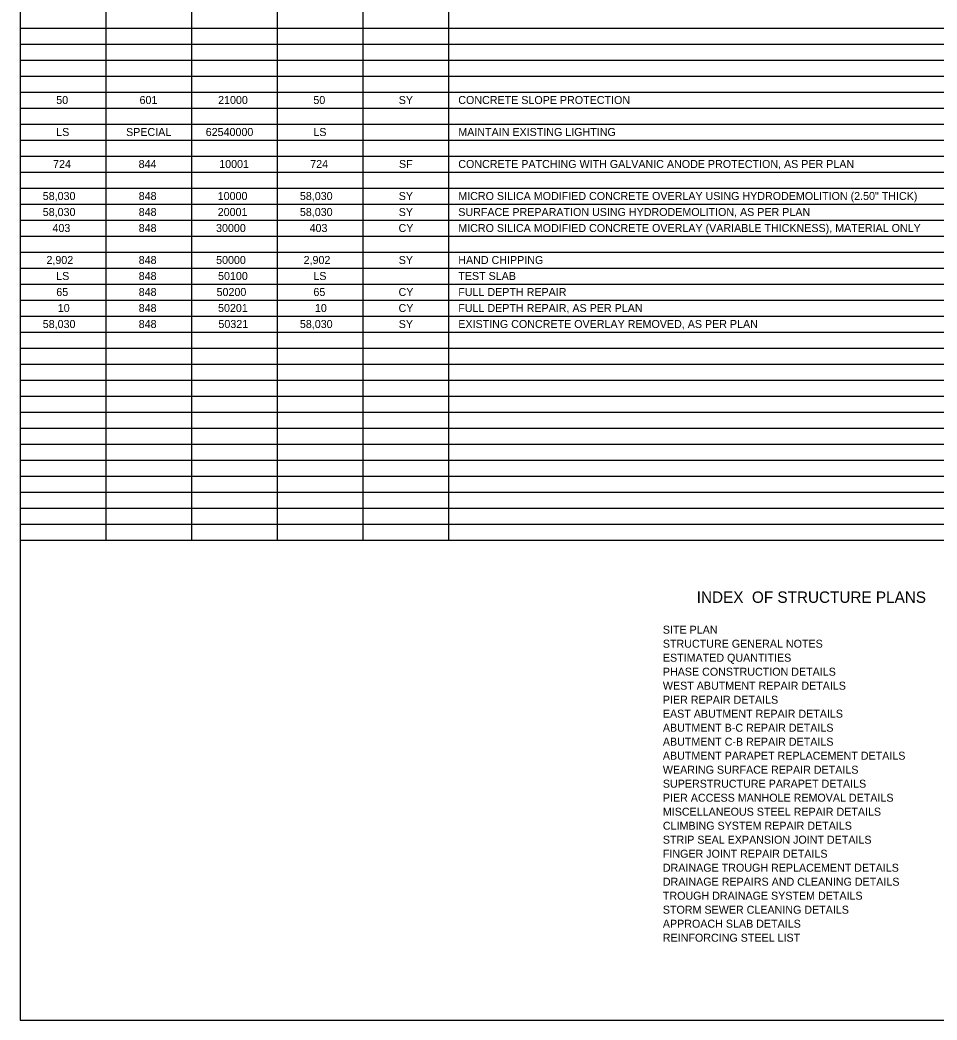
# Model space of a CAD drawing. Extents: x 100 to 128, y 64.8 to 100.
# Drawn here: x 100 to 116.05, y 64.8 to 82.3 of the extents above; entities that cross this region are included whole.
import ezdxf

# ---------------------------------------------------------------- set-up
doc = ezdxf.new("R2010")
doc.units = 0
doc.layers.add('SC_Scratch1', color=7, linetype='Continuous')
doc.layers.add('SH_Text', color=7, linetype='Continuous')

msp = doc.modelspace()

# ---------------------------------------------------------------- linework, layer by layer
at = {"layer": 'SC_Scratch1'}
for p, q in [((100, 73.2), (100, 64.8)), ((100, 64.8), (128, 64.8))]:
    msp.add_line(p, q, dxfattribs=at)
at = {"layer": 'SH_Text'}
for p, q in [((100, 82.44), (100, 82.16)), ((101.5, 82.44), (101.5, 82.16)), ((103, 82.44), (103, 82.16)), ((104.5, 82.44), (104.5, 82.16)), ((106, 82.44), (106, 82.16)), ((107.5, 82.44), (107.5, 82.16)), ((100, 82.16), (128, 82.16)), ((100, 82.16), (100, 81.88)), ((101.5, 82.16), (101.5, 81.88)), ((103, 82.16), (103, 81.88)), ((104.5, 82.16), (104.5, 81.88)), ((106, 82.16), (106, 81.88)), ((107.5, 82.16), (107.5, 81.88)), ((100, 81.88), (128, 81.88)), ((100, 81.88), (100, 81.6)), ((101.5, 81.88), (101.5, 81.6)), ((103, 81.88), (103, 81.6)), ((104.5, 81.88), (104.5, 81.6)), ((106, 81.88), (106, 81.6)), ((107.5, 81.88), (107.5, 81.6)), ((100, 81.6), (128, 81.6)), ((100, 81.6), (100, 81.32)), ((101.5, 81.6), (101.5, 81.32)), ((103, 81.6), (103, 81.32)), ((104.5, 81.6), (104.5, 81.32)), ((106, 81.6), (106, 81.32)), ((107.5, 81.6), (107.5, 81.32)), ((100, 81.32), (128, 81.32)), ((100, 81.32), (100, 81.04)), ((101.5, 81.32), (101.5, 81.04)), ((103, 81.32), (103, 81.04)), ((104.5, 81.32), (104.5, 81.04)), ((106, 81.32), (106, 81.04)), ((107.5, 81.32), (107.5, 81.04)), ((100, 81.04), (128, 81.04)), ((100, 81.04), (100, 80.76)), ((101.5, 81.04), (101.5, 80.76)), ((103, 81.04), (103, 80.76)), ((104.5, 81.04), (104.5, 80.76)), ((106, 81.04), (106, 80.76)), ((107.5, 81.04), (107.5, 80.76)), ((100, 80.76), (128, 80.76)), ((100, 80.76), (100, 80.48)), ((101.5, 80.76), (101.5, 80.48)), ((103, 80.76), (103, 80.48)), ((104.5, 80.76), (104.5, 80.48)), ((106, 80.76), (106, 80.48)), ((107.5, 80.76), (107.5, 80.48)), ((100, 80.48), (128, 80.48)), ((100, 80.48), (100, 80.2)), ((101.5, 80.48), (101.5, 80.2)), ((103, 80.48), (103, 80.2)), ((104.5, 80.48), (104.5, 80.2)), ((106, 80.48), (106, 80.2)), ((107.5, 80.48), (107.5, 80.2)), ((100, 80.2), (128, 80.2)), ((100, 80.2), (100, 79.92)), ((101.5, 80.2), (101.5, 79.92)), ((103, 80.2), (103, 79.92)), ((104.5, 80.2), (104.5, 79.92)), ((106, 80.2), (106, 79.92)), ((107.5, 80.2), (107.5, 79.92)), ((100, 79.92), (128, 79.92)), ((100, 79.92), (100, 79.64)), ((101.5, 79.92), (101.5, 79.64)), ((103, 79.92), (103, 79.64)), ((104.5, 79.92), (104.5, 79.64)), ((106, 79.92), (106, 79.64)), ((107.5, 79.92), (107.5, 79.64)), ((100, 79.64), (128, 79.64)), ((100, 79.64), (100, 79.36)), ((101.5, 79.64), (101.5, 79.36)), ((103, 79.64), (103, 79.36)), ((104.5, 79.64), (104.5, 79.36)), ((106, 79.64), (106, 79.36)), ((107.5, 79.64), (107.5, 79.36)), ((100, 79.36), (128, 79.36)), ((100, 79.36), (100, 79.08)), ((101.5, 79.36), (101.5, 79.08)), ((103, 79.36), (103, 79.08)), ((104.5, 79.36), (104.5, 79.08)), ((106, 79.36), (106, 79.08)), ((107.5, 79.36), (107.5, 79.08)), ((100, 79.08), (128, 79.08)), ((100, 79.08), (100, 78.8)), ((101.5, 79.08), (101.5, 78.8)), ((103, 79.08), (103, 78.8)), ((104.5, 79.08), (104.5, 78.8)), ((106, 79.08), (106, 78.8)), ((107.5, 79.08), (107.5, 78.8)), ((100, 78.8), (128, 78.8)), ((100, 78.8), (100, 78.52)), ((101.5, 78.8), (101.5, 78.52)), ((103, 78.8), (103, 78.52)), ((104.5, 78.8), (104.5, 78.52)), ((106, 78.8), (106, 78.52)), ((107.5, 78.8), (107.5, 78.52)), ((100, 78.52), (128, 78.52)), ((100, 78.52), (100, 78.24)), ((101.5, 78.52), (101.5, 78.24)), ((103, 78.52), (103, 78.24)), ((104.5, 78.52), (104.5, 78.24)), ((106, 78.52), (106, 78.24)), ((107.5, 78.52), (107.5, 78.24)), ((100, 78.24), (128, 78.24)), ((100, 78.24), (100, 77.96)), ((101.5, 78.24), (101.5, 77.96)), ((103, 78.24), (103, 77.96)), ((104.5, 78.24), (104.5, 77.96)), ((106, 78.24), (106, 77.96)), ((107.5, 78.24), (107.5, 77.96)), ((100, 77.96), (128, 77.96)), ((100, 77.96), (100, 77.68)), ((101.5, 77.96), (101.5, 77.68)), ((103, 77.96), (103, 77.68)), ((104.5, 77.96), (104.5, 77.68)), ((106, 77.96), (106, 77.68)), ((107.5, 77.96), (107.5, 77.68)), ((100, 77.68), (128, 77.68)), ((100, 77.68), (100, 77.4)), ((101.5, 77.68), (101.5, 77.4)), ((103, 77.68), (103, 77.4)), ((104.5, 77.68), (104.5, 77.4)), ((106, 77.68), (106, 77.4)), ((107.5, 77.68), (107.5, 77.4)), ((100, 77.4), (128, 77.4)), ((100, 77.4), (100, 77.12)), ((101.5, 77.4), (101.5, 77.12)), ((103, 77.4), (103, 77.12)), ((104.5, 77.4), (104.5, 77.12)), ((106, 77.4), (106, 77.12)), ((107.5, 77.4), (107.5, 77.12)), ((100, 77.12), (128, 77.12)), ((100, 77.12), (100, 76.84)), ((101.5, 77.12), (101.5, 76.84)), ((103, 77.12), (103, 76.84)), ((104.5, 77.12), (104.5, 76.84)), ((106, 77.12), (106, 76.84)), ((107.5, 77.12), (107.5, 76.84)), ((100, 76.84), (128, 76.84)), ((100, 76.84), (100, 76.56)), ((101.5, 76.84), (101.5, 76.56)), ((103, 76.84), (103, 76.56)), ((104.5, 76.84), (104.5, 76.56)), ((106, 76.84), (106, 76.56)), ((107.5, 76.84), (107.5, 76.56)), ((100, 76.56), (128, 76.56)), ((100, 76.56), (100, 76.28)), ((101.5, 76.56), (101.5, 76.28)), ((103, 76.56), (103, 76.28)), ((104.5, 76.56), (104.5, 76.28)), ((106, 76.56), (106, 76.28)), ((107.5, 76.56), (107.5, 76.28)), ((100, 76.28), (128, 76.28)), ((100, 76.28), (100, 76)), ((101.5, 76.28), (101.5, 76)), ((103, 76.28), (103, 76)), ((104.5, 76.28), (104.5, 76)), ((106, 76.28), (106, 76)), ((107.5, 76.28), (107.5, 76)), ((100, 76), (128, 76)), ((100, 76), (100, 75.72)), ((101.5, 76), (101.5, 75.72)), ((103, 76), (103, 75.72)), ((104.5, 76), (104.5, 75.72)), ((106, 76), (106, 75.72)), ((107.5, 76), (107.5, 75.72)), ((100, 75.72), (128, 75.72)), ((100, 75.72), (100, 75.44)), ((101.5, 75.72), (101.5, 75.44)), ((103, 75.72), (103, 75.44)), ((104.5, 75.72), (104.5, 75.44)), ((106, 75.72), (106, 75.44)), ((107.5, 75.72), (107.5, 75.44)), ((100, 75.44), (128, 75.44)), ((100, 75.44), (100, 75.16)), ((101.5, 75.44), (101.5, 75.16)), ((103, 75.44), (103, 75.16)), ((104.5, 75.44), (104.5, 75.16)), ((106, 75.44), (106, 75.16)), ((107.5, 75.44), (107.5, 75.16)), ((100, 75.16), (128, 75.16)), ((100, 75.16), (100, 74.88)), ((101.5, 75.16), (101.5, 74.88)), ((103, 75.16), (103, 74.88)), ((104.5, 75.16), (104.5, 74.88)), ((106, 75.16), (106, 74.88)), ((107.5, 75.16), (107.5, 74.88)), ((100, 74.88), (128, 74.88)), ((100, 74.88), (100, 74.6)), ((101.5, 74.88), (101.5, 74.6)), ((103, 74.88), (103, 74.6)), ((104.5, 74.88), (104.5, 74.6)), ((106, 74.88), (106, 74.6)), ((107.5, 74.88), (107.5, 74.6)), ((100, 74.6), (128, 74.6)), ((100, 74.6), (100, 74.32)), ((101.5, 74.6), (101.5, 74.32)), ((103, 74.6), (103, 74.32)), ((104.5, 74.6), (104.5, 74.32)), ((106, 74.6), (106, 74.32)), ((107.5, 74.6), (107.5, 74.32)), ((100, 74.32), (128, 74.32)), ((100, 74.32), (100, 74.04)), ((101.5, 74.32), (101.5, 74.04)), ((103, 74.32), (103, 74.04)), ((104.5, 74.32), (104.5, 74.04)), ((106, 74.32), (106, 74.04)), ((107.5, 74.32), (107.5, 74.04)), ((100, 74.04), (128, 74.04)), ((100, 74.04), (100, 73.76)), ((101.5, 74.04), (101.5, 73.76)), ((103, 74.04), (103, 73.76)), ((104.5, 74.04), (104.5, 73.76)), ((106, 74.04), (106, 73.76)), ((107.5, 74.04), (107.5, 73.76)), ((100, 73.76), (128, 73.76)), ((100, 73.76), (100, 73.48)), ((101.5, 73.76), (101.5, 73.48)), ((103, 73.76), (103, 73.48)), ((104.5, 73.76), (104.5, 73.48)), ((106, 73.76), (106, 73.48)), ((107.5, 73.76), (107.5, 73.48)), ((100, 73.48), (128, 73.48)), ((100, 73.48), (100, 73.2)), ((101.5, 73.48), (101.5, 73.2)), ((103, 73.48), (103, 73.2)), ((104.5, 73.48), (104.5, 73.2)), ((106, 73.48), (106, 73.2)), ((107.5, 73.48), (107.5, 73.2)), ((100, 73.2), (128, 73.2))]:
    msp.add_line(p, q, dxfattribs=at)

# ---------------------------------------------------------------- texts
for s, height, p in [('50', 0.14, (100.634, 80.83)), ('601', 0.14, (102.092, 80.83)), ('21000', 0.14, (103.467, 80.83)), ('50', 0.14, (105.134, 80.83)), ('SY', 0.14, (106.628, 80.83)), ('CONCRETE SLOPE PROTECTION', 0.14, (107.67, 80.83)), ('LS', 0.14, (100.634, 80.27)), ('SPECIAL', 0.14, (101.856, 80.27)), ('62540000', 0.14, (103.25, 80.27)), ('LS', 0.14, (105.134, 80.27)), ('MAINTAIN EXISTING LIGHTING', 0.14, (107.67, 80.27)), ('724', 0.14, (100.579, 79.71)), ('844', 0.14, (102.076, 79.71)), ('10001', 0.14, (103.486, 79.71)), ('724', 0.14, (105.079, 79.71)), ('SF', 0.14, (106.632, 79.71)), ('CONCRETE PATCHING WITH GALVANIC ANODE PROTECTION, AS PER PLAN', 0.14, (107.67, 79.71)), ('58,030', 0.14, (100.398, 79.15)), ('848', 0.14, (102.077, 79.15)), ('10000', 0.14, (103.46, 79.15)), ('58,030', 0.14, (104.898, 79.15)), ('SY', 0.14, (106.628, 79.15)), ('MICRO SILICA MODIFIED CONCRETE OVERLAY USING HYDRODEMOLITION (2.50" THICK)', 0.14, (107.67, 79.15)), ('58,030', 0.14, (100.398, 78.87)), ('848', 0.14, (102.077, 78.87)), ('20001', 0.14, (103.46, 78.87)), ('58,030', 0.14, (104.898, 78.87)), ('SY', 0.14, (106.628, 78.87)), ('SURFACE PREPARATION USING HYDRODEMOLITION, AS PER PLAN', 0.14, (107.67, 78.87)), ('403', 0.14, (100.568, 78.59)), ('848', 0.14, (102.077, 78.59)), ('30000', 0.14, (103.431, 78.59)), ('403', 0.14, (105.068, 78.59)), ('CY', 0.14, (106.625, 78.59)), ('MICRO SILICA MODIFIED CONCRETE OVERLAY (VARIABLE THICKNESS), MATERIAL ONLY', 0.14, (107.67, 78.59)), ('2,902', 0.14, (100.463, 78.03)), ('848', 0.14, (102.077, 78.03)), ('50000', 0.14, (103.432, 78.03)), ('2,902', 0.14, (104.963, 78.03)), ('SY', 0.14, (106.628, 78.03)), ('HAND CHIPPING', 0.14, (107.67, 78.03)), ('LS', 0.14, (100.634, 77.75)), ('848', 0.14, (102.077, 77.75)), ('50100', 0.14, (103.466, 77.75)), ('LS', 0.14, (105.134, 77.75)), ('TEST SLAB', 0.14, (107.67, 77.75)), ('65', 0.14, (100.635, 77.47)), ('848', 0.14, (102.077, 77.47)), ('50200', 0.14, (103.44, 77.47)), ('65', 0.14, (105.135, 77.47)), ('CY', 0.14, (106.625, 77.47)), ('FULL DEPTH REPAIR', 0.14, (107.67, 77.47)), ('10', 0.14, (100.661, 77.19)), ('848', 0.14, (102.077, 77.19)), ('50201', 0.14, (103.466, 77.19)), ('10', 0.14, (105.161, 77.19)), ('CY', 0.14, (106.625, 77.19)), ('FULL DEPTH REPAIR, AS PER PLAN ', 0.14, (107.67, 77.19)), ('58,030', 0.14, (100.398, 76.91)), ('848', 0.14, (102.077, 76.91)), ('50321', 0.14, (103.472, 76.91)), ('58,030', 0.14, (104.898, 76.91)), ('SY', 0.14, (106.628, 76.91)), ('EXISTING CONCRETE OVERLAY REMOVED, AS PER PLAN', 0.14, (107.67, 76.91)), ('INDEX  OF STRUCTURE PLANS', 0.2, (111.843, 72.1)), ('SITE PLAN', 0.14, (111.25, 71.56)), ('STRUCTURE GENERAL NOTES', 0.14, (111.25, 71.315)), ('ESTIMATED QUANTITIES', 0.14, (111.25, 71.07)), ('PHASE CONSTRUCTION DETAILS', 0.14, (111.25, 70.825)), ('WEST ABUTMENT REPAIR DETAILS', 0.14, (111.25, 70.58)), ('PIER REPAIR DETAILS', 0.14, (111.25, 70.335)), ('EAST ABUTMENT REPAIR DETAILS', 0.14, (111.25, 70.09)), ('ABUTMENT B-C REPAIR DETAILS', 0.14, (111.25, 69.845)), ('ABUTMENT C-B REPAIR DETAILS', 0.14, (111.25, 69.6)), ('ABUTMENT PARAPET REPLACEMENT DETAILS', 0.14, (111.25, 69.355)), ('WEARING SURFACE REPAIR DETAILS', 0.14, (111.25, 69.11)), ('SUPERSTRUCTURE PARAPET DETAILS', 0.14, (111.25, 68.865)), ('PIER ACCESS MANHOLE REMOVAL DETAILS', 0.14, (111.25, 68.62)), ('MISCELLANEOUS STEEL REPAIR DETAILS', 0.14, (111.25, 68.375)), ('CLIMBING SYSTEM REPAIR DETAILS', 0.14, (111.25, 68.13)), ('STRIP SEAL EXPANSION JOINT DETAILS', 0.14, (111.25, 67.885)), ('FINGER JOINT REPAIR DETAILS', 0.14, (111.25, 67.64)), ('DRAINAGE TROUGH REPLACEMENT DETAILS', 0.14, (111.25, 67.395)), ('DRAINAGE REPAIRS AND CLEANING DETAILS', 0.14, (111.25, 67.15)), ('TROUGH DRAINAGE SYSTEM DETAILS', 0.14, (111.25, 66.905)), ('STORM SEWER CLEANING DETAILS', 0.14, (111.25, 66.66)), ('APPROACH SLAB DETAILS', 0.14, (111.25, 66.415)), ('REINFORCING STEEL LIST', 0.14, (111.25, 66.17))]:
    msp.add_text(s, height=height, dxfattribs=at).set_placement(p)

doc.saveas('drawing.dxf')
